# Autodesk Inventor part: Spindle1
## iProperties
Shininess: 94.0
Length Units: 11269
Angle Units: 11279
Time Units: 11290
Mass Units: 11283
Length Display Precision: 3
Angle Display Precision: 2
Created: 2004-12
Part Number: Spindle1
Description: Spindle.ipt.
Document SubType Name: Modeling
Designer: DA
Material: NICU, Monel 400
Density: 8.83 g/cm^3
Density: 0.0
Volumn: 0.0
Area: 0.0
PropertySet Name: Model Information
Control State: 0
Master: False
Checked Out: False
ProtocolID: P00010905134112116
Protocol: P00010905134112116<@PID>[Version]<@EL>Version=2.0<@EL>[BaseView]<@EL>EnableUpdate=<@EL>InOpt=0<@EL>UpdateAll=0<@EL>OnTop=0<@EL>Left=479<@EL>Top=280<@EL>W2=350<@
Author: Autodesk
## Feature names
1. Extrusion1
2. Extrusion3
3. Fillet1
4. Extrusion4
5. Revolution1
6. Extrusion5
7. Hole1
8. Circular Pattern2
9. Extrusion7
